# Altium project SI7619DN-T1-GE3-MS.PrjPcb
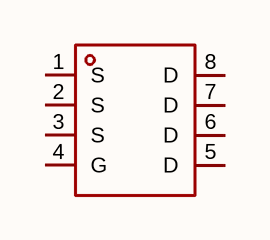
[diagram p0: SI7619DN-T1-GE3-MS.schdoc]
1 sheet, 1 parts. Net scope: global (net labels, ports and power ports of the same name join across sheets).

## Sheet SI7619DN-T1-GE3-MS.schdoc
size 127 x 101 mm

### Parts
Q?  si7619dn-t1-ge3-ms  [POWERPAK-1212-8_L3.0-W3.0-P0.65-LS3.3-BL]  (value not drawn)

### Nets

Not connected (* = marked no-connect by the designer): Q? 1(S) 2(S) 3(S) 4(G) 5(D) 6(D) 7(D) 8(D)

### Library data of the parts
Q? = si7619dn-t1-ge3-ms: 数量:1个P沟道;漏源电压(Vdss):30V;连续漏极电流(Id):25A;导通电阻(RDS(on)):16mΩ@10V;耗散功率(Pd):29W;阈值电压(Vgs(th)):1V;; Manufacturer: MSKSEMI(美森科); AddInBom: yes; ModelId: 74fc8db97a8d4d328d7f3b4acba39a5e; ModelTransform: 129.921,129.921,0,0,0,0,0,0,0; Number: 1个P沟道; Drain to Source Voltage: 30V; Current - Continuous Drain(Id): 25A; Pd - Power Dissipation: 29W; Gate Threshold Voltage (Vgs(th)): 1V; Gate Charge(Qg): 52nC; Input Capacitance(Ciss): 1.15nF; Reverse Transfer Capacitance (Crss@Vds): 134pF; Configuration: 独立式; Type: P沟道; Output Capacitance(Coss): 150pF; Vgs: ±20V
